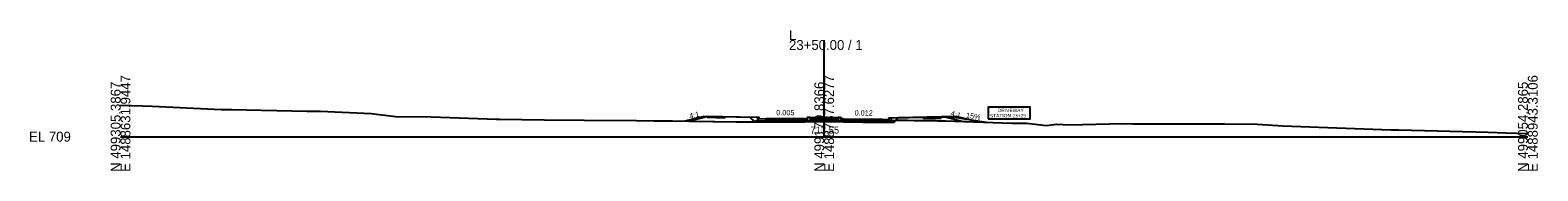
# Model space of a CAD drawing. Extents: x -26 to 4203, y -10 to 9538.
# Drawn here: x 974.3 to 1402.8, y 2490.3 to 2530.2 of the extents above; entities that cross this region are included whole.
import ezdxf

# ---------------------------------------------------------------- set-up
doc = ezdxf.new("R2010")
doc.units = 0
for name, color, linetype in [('Default', 7, 'Continuous'), ('Exist Horizontal Alignment', 7, 'Continuous'), ('Prop Grid Mask', 7, 'Continuous'), ('Prop Horizontal Alignment', 7, 'Continuous'), ('Prop Horizontal Alignment Curve and Spiral Data', 7, 'Continuous'), ('Prop Horizontal Alignment Station Label', 7, 'Continuous'), ('Prop Horizontal Alignment Tick Label', 7, 'Continuous'), ('Prop Horizontal Alignment Tick Large', 7, 'Continuous'), ('Prop Horizontal Alignment Tick Small', 7, 'Continuous'), ('Prop Lane Lines', 7, 'Continuous'), ('Scratch_Level_2', 7, 'Continuous'), ('Scratch_Level_4', 7, 'Continuous'), ('Scratch_Level_5', 7, 'Continuous'), ('Sheet Border Standard 30in CELL', 7, 'Continuous'), ('Sheet Cutting Line CELL', 7, 'Continuous'), ('Sheet Data Field CELL', 7, 'Continuous'), ('Sheet Plot Border Inside CELL', 7, 'Continuous'), ('Sheet Plot Border Outside CELL', 7, 'Continuous')]:
    doc.layers.add(name, color=color, linetype=linetype)

msp = doc.modelspace()

# ---------------------------------------------------------------- linework, layer by layer
at = {"layer": 'Exist Horizontal Alignment'}
msp.add_lwpolyline([(1000, 2508.99), (1006.28, 2508.77), (1008.95, 2508.69), (1028.57, 2507.7), (1031.52, 2507.68), (1052.92, 2507.24), (1056.85, 2507.22), (1071.26, 2506.59), (1078.15, 2505.68), (1088.24, 2505.59), (1106.88, 2504.95), (1107.71, 2504.95), (1120.44, 2504.74), (1131.76, 2504.71), (1146.66, 2504.62), (1151.66, 2504.52), (1156.86, 2504.48), (1174.98, 2504.21), (1187.72, 2504.2), (1192.08, 2504.27), (1194.09, 2504.37), (1196.05, 2504.46), (1200.24, 2504.55), (1203.05, 2504.56), (1203.72, 2504.56), (1205.13, 2504.57), (1206.26, 2504.58), (1206.9, 2504.58), (1207.7, 2504.59), (1208.68, 2504.59), (1209.47, 2504.6), (1210.46, 2504.61), (1211.69, 2504.61), (1212.24, 2504.6), (1212.68, 2504.61), (1214.02, 2504.6), (1215.89, 2504.61), (1217.57, 2504.62), (1219.35, 2504.63), (1219.65, 2504.63), (1222.32, 2504.65), (1222.91, 2504.65), (1223.63, 2504.64), (1225.53, 2504.63), (1226.46, 2504.62), (1227.62, 2504.61), (1228.24, 2504.61), (1228.74, 2504.6), (1230.02, 2504.58), (1231.6, 2504.55), (1232.27, 2504.52), (1233.27, 2504.49), (1234.44, 2504.48), (1253.35, 2503.88), (1254.01, 2503.86), (1257.48, 2503.88), (1263.2, 2503.13), (1266.02, 2503.51), (1269.7, 2503.37), (1284.76, 2503.7), (1287.75, 2503.62), (1307.5, 2503.69), (1310.81, 2503.66), (1313.9, 2503.62), (1323.1, 2503.51), (1330.34, 2503.07), (1332.89, 2502.97), (1361.08, 2501.96), (1363.32, 2501.92), (1388.72, 2501.3), (1393.71, 2501.11), (1400, 2500.91)], dxfattribs=at)
at = {"layer": 'Prop Horizontal Alignment Curve and Spiral Data'}
for points in [[(1183.5, 2504.21), (1180.25, 2504.19), (1178.95, 2505.49)], [(1194.5, 2504.22), (1183.5, 2504.17)], [(1183.5, 2504.17), (1183.5, 2504.21)], [(1196.76, 2504.31), (1194.5, 2504.26)], [(1194.5, 2504.26), (1194.5, 2504.22)], [(1194.5, 2504.22), (1194.5, 2504.22)], [(1196.76, 2504.31), (1203.24, 2504.27)], [(1203.24, 2504.27), (1205.5, 2504.23)], [(1205.5, 2504.23), (1205.5, 2504.19)], [(1205.5, 2504.19), (1216.5, 2504.06)], [(1205.5, 2504.19), (1205.5, 2504.19)], [(1216.5, 2504.1), (1219.75, 2504.06), (1221.06, 2505.37)], [(1216.5, 2504.06), (1216.5, 2504.1)]]:
    msp.add_lwpolyline(points, dxfattribs=at)
at = {"layer": 'Prop Horizontal Alignment Station Label'}
for p, q in [((1165.75, 2505.76), (1160.43, 2504.43)), ((1234.25, 2505.63), (1239.52, 2504.32))]:
    msp.add_line(p, q, dxfattribs=at)
for points in [[(1181, 2505.45), (1165.75, 2505.76)], [(1219, 2505.33), (1234.25, 2505.63)]]:
    msp.add_lwpolyline(points, dxfattribs=at)
at = {"layer": 'Prop Horizontal Alignment Tick Label'}
for points in [[(1194.5, 2504.85), (1183.5, 2504.79)], [(1183.5, 2504.79), (1183.5, 2504.54)], [(1183.5, 2504.54), (1194.5, 2504.6)], [(1194.5, 2504.6), (1194.5, 2504.85)], [(1205.5, 2504.81), (1216.5, 2504.68)], [(1205.5, 2504.56), (1205.5, 2504.81)], [(1216.5, 2504.43), (1205.5, 2504.56)], [(1216.5, 2504.68), (1216.5, 2504.43)]]:
    msp.add_lwpolyline(points, dxfattribs=at)
at = {"layer": 'Prop Horizontal Alignment Tick Large'}
for points in [[(1194.5, 2504.6), (1183.5, 2504.54)], [(1183.5, 2504.54), (1183.5, 2504.17)], [(1183.5, 2504.17), (1194.5, 2504.22)], [(1194.5, 2504.22), (1194.5, 2504.6)], [(1205.5, 2504.56), (1216.5, 2504.43)], [(1205.5, 2504.19), (1205.5, 2504.56)], [(1216.5, 2504.06), (1205.5, 2504.19)], [(1216.5, 2504.43), (1216.5, 2504.06)]]:
    msp.add_lwpolyline(points, dxfattribs=at)
at = {"layer": 'Prop Horizontal Alignment Tick Small'}
for p, q in [((1166.75, 2505.4), (1166.75, 2505.74)), ((1171.75, 2505.3), (1166.75, 2505.4)), ((1171.75, 2505.3), (1171.75, 2505.64)), ((1196.01, 2505.11), (1203.99, 2505.08)), ((1228.25, 2505.18), (1228.25, 2505.51)), ((1228.25, 2505.18), (1233.25, 2505.28)), ((1233.25, 2505.28), (1233.25, 2505.61))]:
    msp.add_line(p, q, dxfattribs=at)
for points in [[(1183.5, 2505.04), (1181.5, 2504.95), (1181.5, 2505.45), (1181, 2505.45)], [(1181, 2505.45), (1181, 2504.45), (1183.5, 2504.46)], [(1183.5, 2504.46), (1183.5, 2505.04)], [(1194.5, 2505.1), (1195.25, 2505.11), (1195.25, 2505.53), (1196.01, 2505.53)], [(1194.5, 2504.51), (1194.5, 2505.1)], [(1196.01, 2504.54), (1194.5, 2504.51)], [(1196.01, 2505.53), (1196.01, 2504.54)], [(1196.01, 2505.53), (1203.99, 2505.49)], [(1203.99, 2505.49), (1203.99, 2504.51)], [(1203.99, 2504.51), (1205.5, 2504.48)], [(1205.5, 2504.48), (1205.5, 2505.06)], [(1216.5, 2504.93), (1218.5, 2504.83), (1218.5, 2505.33), (1219, 2505.33)], [(1219, 2505.33), (1219, 2504.32), (1216.5, 2504.35)], [(1216.5, 2504.35), (1216.5, 2504.93)]]:
    msp.add_lwpolyline(points, dxfattribs=at)
at = {"layer": 'Prop Lane Lines'}
for p, q in [((1232.5, 2505.6), (1237.5, 2505.4)), ((1237.5, 2505.4), (1246.11, 2504.11))]:
    msp.add_line(p, q, dxfattribs=at)
at = {"layer": 'Scratch_Level_2'}
msp.add_lwpolyline([(1246.57, 2505.02), (1258.53, 2505.02), (1258.53, 2508.41), (1246.57, 2508.41)], close=True, dxfattribs=at)
at = {"layer": 'Scratch_Level_4'}
for p, q in [((1200, 2500), (1200, 2527.43)), ((1000, 2500), (1200, 2500)), ((1200, 2500), (1400, 2500))]:
    msp.add_line(p, q, dxfattribs=at)
at = {"layer": 'Sheet Border Standard 30in CELL'}
for points in [[(1194.5, 2505.1), (1183.5, 2505.04)], [(1205.5, 2505.06), (1216.5, 2504.93)]]:
    msp.add_lwpolyline(points, dxfattribs=at)
at = {"layer": 'Sheet Cutting Line CELL'}
for points in [[(1180.23, 2504.21), (1178.95, 2505.49), (1167, 2505.73), (1161.7, 2504.41), (1174.98, 2504.21)], [(1183.5, 2504.21), (1180.25, 2504.19), (1180.23, 2504.21)], [(1203.05, 2504.56), (1203.72, 2504.56), (1205.13, 2504.57), (1206.26, 2504.58), (1206.9, 2504.58), (1207.7, 2504.59), (1208.68, 2504.59), (1209.47, 2504.6), (1210.46, 2504.61), (1211.69, 2504.61), (1212.24, 2504.6), (1212.68, 2504.61), (1214.02, 2504.6), (1215.89, 2504.61), (1217.57, 2504.62), (1219.35, 2504.63), (1219.65, 2504.63), (1220.33, 2504.64), (1219.75, 2504.06), (1216.5, 2504.1), (1216.5, 2504.06), (1200, 2504.25), (1183.5, 2504.17), (1183.5, 2504.21), (1187.72, 2504.2), (1192.08, 2504.27), (1194.09, 2504.37), (1196.05, 2504.46), (1200.24, 2504.55)], [(1234.44, 2504.48), (1243.54, 2504.19), (1237.5, 2505.7), (1221.06, 2505.37), (1220.33, 2504.64), (1222.32, 2504.65), (1222.91, 2504.65), (1223.63, 2504.64), (1225.53, 2504.63), (1226.46, 2504.62), (1227.62, 2504.61), (1228.24, 2504.61), (1228.74, 2504.6), (1230.02, 2504.58), (1231.6, 2504.55), (1232.27, 2504.52), (1233.27, 2504.49)]]:
    msp.add_lwpolyline(points, close=True, dxfattribs=at)
at = {"layer": 'Sheet Data Field CELL'}
for points in [[(1183.5, 2504.46), (1180.5, 2504.44), (1180.25, 2504.19)], [(1180.25, 2504.19), (1183.5, 2504.21)], [(1183.5, 2504.21), (1183.5, 2504.46)], [(1194.5, 2504.51), (1196.51, 2504.55), (1196.76, 2504.31)], [(1194.5, 2504.26), (1194.5, 2504.51)], [(1196.76, 2504.31), (1194.5, 2504.26)], [(1205.5, 2504.48), (1203.49, 2504.52), (1203.24, 2504.27)], [(1203.24, 2504.27), (1205.5, 2504.23)], [(1205.5, 2504.23), (1205.5, 2504.48)], [(1216.5, 2504.35), (1219.5, 2504.31), (1219.75, 2504.06)], [(1216.5, 2504.1), (1216.5, 2504.35)], [(1219.75, 2504.06), (1216.5, 2504.1)]]:
    msp.add_lwpolyline(points, dxfattribs=at)
at = {"layer": 'Sheet Plot Border Inside CELL'}
for points in [[(1194.5, 2505.1), (1183.5, 2505.04)], [(1183.5, 2505.04), (1183.5, 2504.79)], [(1183.5, 2504.79), (1194.5, 2504.85)], [(1194.5, 2504.85), (1194.5, 2505.1)], [(1194.5, 2504.85), (1194.5, 2504.85), (1194.5, 2504.85)], [(1205.5, 2505.06), (1216.5, 2504.93)], [(1205.5, 2504.81), (1205.5, 2505.06)], [(1216.5, 2504.68), (1205.5, 2504.81)], [(1205.5, 2504.81), (1205.5, 2504.81), (1205.5, 2504.81)], [(1216.5, 2504.93), (1216.5, 2504.68)]]:
    msp.add_lwpolyline(points, dxfattribs=at)
at = {"layer": 'Sheet Plot Border Outside CELL'}
for points in [[(1181.5, 2504.95), (1181.5, 2505.45), (1181, 2505.45)], [(1183.5, 2505.04), (1181.5, 2504.95)], [(1205.5, 2505.06), (1204.75, 2505.08), (1204.75, 2505.49), (1203.99, 2505.49)], [(1216.5, 2504.93), (1218.5, 2504.83)], [(1218.5, 2504.83), (1218.5, 2505.33), (1219, 2505.33)]]:
    msp.add_lwpolyline(points, dxfattribs=at)

# ---------------------------------------------------------------- texts
at = {"layer": 'Default'}
msp.add_text('-', height=0.0001, dxfattribs=at).set_placement((1000, 2500))
msp.add_text('-', height=0.0001, dxfattribs=at).set_placement((1000, 2500))
msp.add_text('-', height=0.0001, dxfattribs=at).set_placement((1000, 2500))
at = {"layer": 'Prop Grid Mask'}
for s, rotation, p in [('4:1', 14.0362, (1161.85, 2505.05)), ('4:1', 345.9638, (1235.83, 2505.97)), ('15%', 352.0623, (1240.22, 2505.34))]:
    msp.add_text(s, height=1.5, rotation=rotation, dxfattribs=at).set_placement(p)
at = {"layer": 'Prop Horizontal Alignment'}
msp.add_text('713.55', height=2, dxfattribs=at).set_placement((1196.07, 2500.88))
at = {"layer": 'Scratch_Level_4'}
for s, p in [('L', (1190, 2527.43)), ('23+50.00 / 1', (1190, 2524.63)), ('EL 709', (974, 2498.6))]:
    msp.add_text(s, height=2.8, dxfattribs=at).set_placement(p)
for s, p in [('E 1488631.9447', (1002.8, 2490)), ('E 1488787.6277', (1202.8, 2490)), ('E 1488943.3106', (1402.8, 2490)), ('N 499305.3867', (1000, 2490)), ('N 499179.8366', (1200, 2490)), ('N 499054.2865', (1400, 2490))]:
    msp.add_text(s, height=2.8, rotation=90, dxfattribs=at).set_placement(p)
at = {"layer": 'Scratch_Level_5'}
for s, height, rotation, p in [('0.005', 1.5, 0.2865, (1186.38, 2506.06)), ('0.012', 1.5, 359.3316, (1208.62, 2506.02)), ('DRIVEWAY', 1, 360, (1249.35, 2506.96)), ('STATION 23+25', 1, 360, (1247.1, 2505.46))]:
    msp.add_text(s, height=height, rotation=rotation, dxfattribs=at).set_placement(p)

doc.saveas('drawing.dxf')
